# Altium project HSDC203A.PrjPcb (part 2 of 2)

## Sheet HSDC203A_Hub_EZFET.SchDoc: USB Hub and EZFET
size 431 x 279 mm; Date: Not shown in title block; ApprovedBy: Not shown in title block; CheckedBy: Not shown in title block; Author: Not shown in title block; CompanyName: Not shown in title block; Engineer: Not shown in title block; Organization: Not shown in title block; Address1: Not shown in title block; Address2: Not shown in title block; Address3: Not shown in title block; Address4: Not shown in title block; DocumentNumber: 2; Revision: Use project parameter SCH_Rev; SheetNumber: 4; SheetTotal: 7; PageSetup: Record=PageOptions¦CenterHorizontal=True¦CenterVertical=True¦PrintScale=1.00¦XCorrection=1.00¦YCorrection=1.00¦PrintKind=0¦BorderSize=5000000¦LeftOffset=0¦BottomOffset=0¦Orientation=2¦PaperLength=1000¦PaperWidth=1000¦Scale=100¦PaperSource=15¦PrintQuality=600¦MediaType=1¦DitherType=10¦PaperKind=Letter¦PrintScaleMode=1
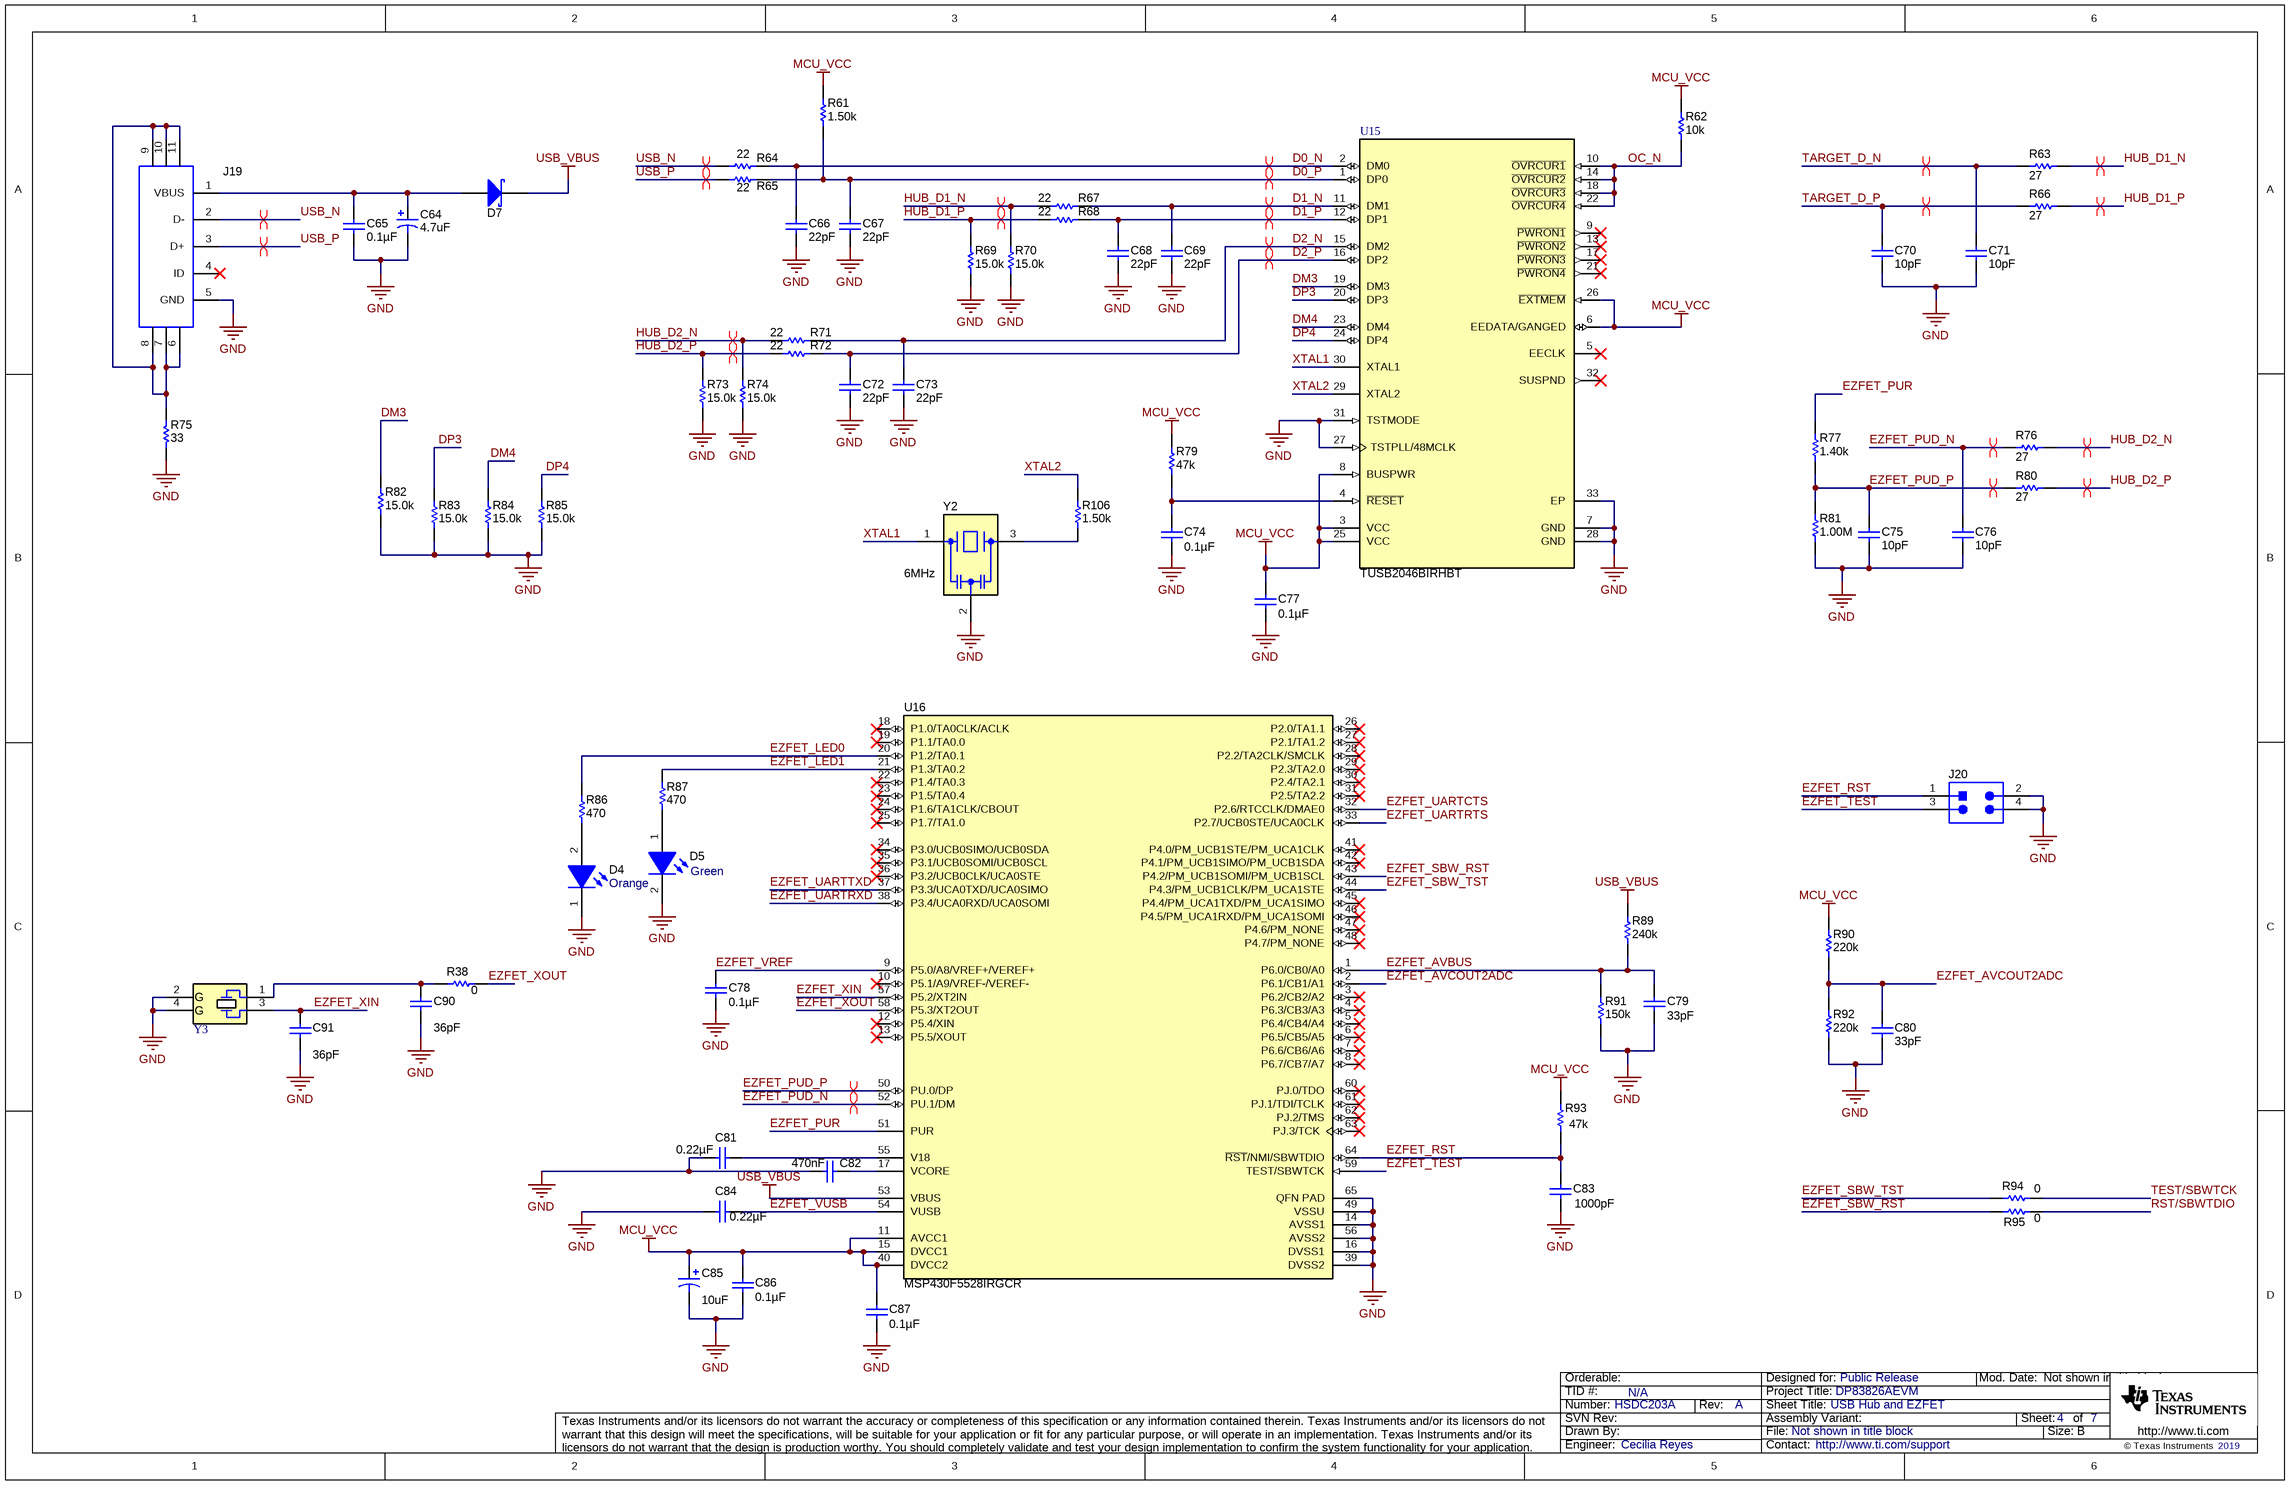
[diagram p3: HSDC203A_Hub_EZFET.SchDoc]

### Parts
C64  ValueDisplayed: 4.7uF  [7343-31]  (hidden comment: 293D475X9035D2TE3)
C65  ValueDisplayed: 0.1µF  [0402]  (hidden comment: C0402C104K8RACTU)
C66  ValueDisplayed: 22pF  [0402]  (hidden comment: C1005NP01H220J050BA)
C67  ValueDisplayed: 22pF  [0402]  (hidden comment: C1005NP01H220J050BA)
C68  ValueDisplayed: 22pF  [0402]  (hidden comment: C1005NP01H220J050BA)
C69  ValueDisplayed: 22pF  [0402]  (hidden comment: C1005NP01H220J050BA)
C70  ValueDisplayed: 10pF  [0603]  (hidden comment: CGA3E2NP01H100D080AA)
C71  ValueDisplayed: 10pF  [0603]  (hidden comment: CGA3E2NP01H100D080AA)
C72  ValueDisplayed: 22pF  [0402]  (hidden comment: C1005NP01H220J050BA)
C73  ValueDisplayed: 22pF  [0402]  (hidden comment: C1005NP01H220J050BA)
C74  ValueDisplayed: 0.1µF  [0402]  (hidden comment: CL05B104KO5NNNC)
C75  ValueDisplayed: 10pF  [0603]  (hidden comment: CGA3E2NP01H100D080AA)
C76  ValueDisplayed: 10pF  [0603]  (hidden comment: CGA3E2NP01H100D080AA)
C77  ValueDisplayed: 0.1µF  [0402]  (hidden comment: CL05B104KO5NNNC)
C78  ValueDisplayed: 0.1µF  [0402]  (hidden comment: CL05B104KO5NNNC)
C79  ValueDisplayed: 33pF  [0402]  (hidden comment: GCM1555C1H330JA16D)
C80  ValueDisplayed: 33pF  [0402]  (hidden comment: GCM1555C1H330JA16D)
C81  ValueDisplayed: 0.22µF  [0603]  (hidden comment: CL10A224KB8NNNC)
C82  Cap_F: 470nF  [0603]  (hidden comment: CGA3E3X7R1H474K080AB)
C83  ValueDisplayed: 1000pF  [0402]  (hidden comment: C1005NP01H102J050BA)
C84  ValueDisplayed: 0.22µF  [0603]  (hidden comment: CL10A224KB8NNNC)
C85  ValueDisplayed: 10uF  [7343-31]  (hidden comment: TPSD106K035R0125)
C86  ValueDisplayed: 0.1µF  [0402]  (hidden comment: CL05B104KO5NNNC)
C87  ValueDisplayed: 0.1µF  [0402]  (hidden comment: CL05B104KO5NNNC)
C90  ValueDisplayed: 36pF  [0402]  (hidden comment: CL05C360JB5NNNC)
C91  ValueDisplayed: 36pF  [0402]  (hidden comment: CL05C360JB5NNNC)
D4  value Orange  [APHHS1005_Orange]  (hidden comment: APHHS1005SECK)
D5  value Green  [QTLP630C_Green]  (hidden comment: QTLP630C4TR)
D7  NRVBA160T3G  [SMA]  (value not drawn)
J19  475890001  [Molex_0475890001]  (value not drawn)
J20  TSW-102-07-G-D  [TSW-102-07-G-D]  (value not drawn)
R38  ValueDisplayed: 0  [0402]  (hidden comment: RC0402JR-070RL)
R61  ValueDisplayed: 1.50k  [0402]  (hidden comment: CRCW04021K50FKED)
R62  ValueDisplayed: 10k  [0402]  (hidden comment: CRCW040210K0JNED)
R63  ValueDisplayed: 27  [0402]  (hidden comment: CRCW040227R0JNED)
R64  ValueDisplayed: 22  [0402]  (hidden comment: CRCW040222R0JNED)
R65  ValueDisplayed: 22  [0402]  (hidden comment: CRCW040222R0JNED)
R66  ValueDisplayed: 27  [0402]  (hidden comment: CRCW040227R0JNED)
R67  ValueDisplayed: 22  [0402]  (hidden comment: CRCW040222R0JNED)
R68  ValueDisplayed: 22  [0402]  (hidden comment: CRCW040222R0JNED)
R69  ValueDisplayed: 15.0k  [0402]  (hidden comment: CRCW040215K0FKED)
R70  ValueDisplayed: 15.0k  [0402]  (hidden comment: CRCW040215K0FKED)
R71  ValueDisplayed: 22  [0402]  (hidden comment: CRCW040222R0JNED)
R72  ValueDisplayed: 22  [0402]  (hidden comment: CRCW040222R0JNED)
R73  ValueDisplayed: 15.0k  [0402]  (hidden comment: CRCW040215K0FKED)
R74  ValueDisplayed: 15.0k  [0402]  (hidden comment: CRCW040215K0FKED)
R75  ValueDisplayed: 33  [0402]  (hidden comment: CRCW040233R0JNED)
R76  ValueDisplayed: 27  [0402]  (hidden comment: CRCW040227R0JNED)
R77  ValueDisplayed: 1.40k  [0402]  (hidden comment: CRCW04021K40FKED)
R79  ValueDisplayed: 47k  [0402]  (hidden comment: CRCW040247K0JNED)
R80  ValueDisplayed: 27  [0402]  (hidden comment: CRCW040227R0JNED)
R81  ValueDisplayed: 1.00M  [0402]  (hidden comment: CRCW04021M00FKED)
R82  ValueDisplayed: 15.0k  [0402]  (hidden comment: CRCW040215K0FKED)
R83  ValueDisplayed: 15.0k  [0402]  (hidden comment: CRCW040215K0FKED)
R84  ValueDisplayed: 15.0k  [0402]  (hidden comment: CRCW040215K0FKED)
R85  ValueDisplayed: 15.0k  [0402]  (hidden comment: CRCW040215K0FKED)
R86  ValueDisplayed: 470  [0402]  (hidden comment: CRCW0402470RJNED)
R87  ValueDisplayed: 470  [0402]  (hidden comment: CRCW0402470RJNED)
R89  ValueDisplayed: 240k  [0402]  (hidden comment: CRCW0402240KJNED)
R90  ValueDisplayed: 220k  [0402]  (hidden comment: CRCW0402220KJNED)
R91  ValueDisplayed: 150k  [0402]  (hidden comment: CRCW0402150KJNED)
R92  ValueDisplayed: 220k  [0402]  (hidden comment: CRCW0402220KJNED)
R93  ValueDisplayed: 47k  [0402]  (hidden comment: CRCW040247K0JNED)
R94  ValueDisplayed: 0  [0402]  (hidden comment: RC0402JR-070RL)
R95  ValueDisplayed: 0  [0402]  (hidden comment: RC0402JR-070RL)
R106  ValueDisplayed: 1.50k  [0402]  (hidden comment: CRCW04021K50FKED)
U15  TUSB2046BIRHBT  [RHB0032E]
U16  MSP430F5528IRGCR  [RGC0064B]
Y2  Frequency_Fixed: 6MHz  [Murata_CSTCR_G]  (hidden comment: CSTCR6M00G53Z-R0)
Y3  ECS-240-20-33-DU-TR  [ECS_ECX-32]  (value not drawn)

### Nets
GND: C64.2(-) C65.1 C66.2 C67.2 C68.2 C69.2 C70.1 C71.1 C72.2 C73.2 C74.2 C75.2 C76.2 C77.2 C78.2 C79.2 C80.2 C81.2 C82.2 C83.2 C84.2 C85.2(-) C86.2 C87.2 C90.2 C91.2 D4.1(K) D5.2(K) J19.5(GND) J20.2 J20.4 R69.1 R70.1 R73.1 R74.1 R75.2 R81.1 R82.1 R83.1 R84.1 R85.1 R91.1 R92.1 U15.7(GND) U15.27(TSTPLL/48MCLK) U15.28(GND) U15.31(TSTMODE) U15.33(EP) U16.14(AVSS1) U16.16(DVSS1) U16.39(DVSS2) U16.49(VSSU) U16.56(AVSS2) U16.65(QFN_PAD) Y2.2(GND) Y3.2(GND) Y3.4(GND)
MCU_VCC: C77.1 C85.1(+) C86.1 C87.1 R61.2 R62.2 R79.2 R90.2 R93.2 U15.3(VCC) U15.6(EEDATA/GANGED) U15.8(BUSPWR) U15.25(VCC) U15.26(~{EXTMEM}) U16.11(AVCC1) U16.15(DVCC1) U16.40(DVCC2)
USB_VBUS: D7.1(K) R89.2 U16.53(VBUS)
D0_N: C66.1 R64.2 U15.2(DM0)
D0_P: C67.1 R61.1 R65.2 U15.1(DP0)
D1_N: C69.1 R67.2 U15.11(DM1)
D1_P: C68.1 R68.2 U15.12(DP1)
D2_N: C73.1 R71.2 U15.15(DM2)
D2_P: C72.1 R72.2 U15.16(DP2)
DM3: R82.2 U15.19(DM3)
DM4: R84.2 U15.23(DM4)
DP3: R83.2 U15.20(DP3)
DP4: R85.2 U15.24(DP4)
EZFET_AVBUS: C79.1 R89.1 R91.2 U16.1(P6.0/CB0/A0)
EZFET_AVCOUT2ADC: C80.1 R90.1 R92.2 U16.2(P6.1/CB1/A1)
EZFET_LED0: R86.2 U16.20(P1.2/TA0.1)
EZFET_LED1: R87.2 U16.21(P1.3/TA0.2)
EZFET_PUD_N: C76.1 R76.1 U16.52(PU.1/DM)
EZFET_PUD_P: C75.1 R77.1 R80.1 R81.2 U16.50(PU.0/DP)
EZFET_PUR: R77.2 U16.51(PUR)
EZFET_RST: C83.1 J20.1 R93.1 U16.64(~{RST}/NMI/SBWTDIO)
EZFET_SBW_RST: R95.1 U16.43(P4.2/PM_UCB1SOMI/PM_UCB1SCL)
EZFET_SBW_TST: R94.1 U16.44(P4.3/PM_UCB1CLK/PM_UCA1STE)
EZFET_TEST: J20.3 U16.59(TEST/SBWTCK)
EZFET_UARTCTS: U16.32(P2.6/RTCCLK/DMAE0)
EZFET_UARTRTS: U16.33(P2.7/UCB0STE/UCA0CLK)
EZFET_UARTRXD: U16.38(P3.4/UCA0RXD/UCA0SOMI)
EZFET_UARTTXD: U16.37(P3.3/UCA0TXD/UCA0SIMO)
EZFET_VREF: C78.1 U16.9(P5.0/A8/VREF+/VEREF+)
EZFET_VUSB: C84.1 U16.54(VUSB)
EZFET_XIN: C91.1 U16.57(P5.2/XT2IN) Y3.3
EZFET_XOUT: R38.2 U16.58(P5.3/XT2OUT)
HUB_D1_N: R63.2 R67.1 R70.2
HUB_D1_P: R66.2 R68.1 R69.2
HUB_D2_N: R71.1 R74.2 R76.2
HUB_D2_P: R72.1 R73.2 R80.2
OC_N: R62.1 U15.10(~{OVRCUR1}) U15.14(~{OVRCUR2}) U15.18(~{OVRCUR3}) U15.22(~{OVRCUR4})
RST/SBWTDIO: R95.2
TARGET_D_N: C71.2 R63.1
TARGET_D_P: C70.2 R66.1
TEST/SBWTCK: R94.2
USB_N: J19.2(D-) R64.1
USB_P: J19.3(D+) R65.1
XTAL1: U15.30(XTAL1) Y2.1(In)
XTAL2: R106.2 U15.29(XTAL2)
NetC64_1: C64.1(+) C65.2 D7.2(A) J19.1(VBUS)
NetC74_1: C74.1 R79.1 U15.4(~{RESET})
NetC81_1: C81.1 U16.55(V18)
NetC82_1: C82.1 U16.17(VCORE)
NetC90_1: C90.1 R38.1 Y3.1
NetD4_2: D4.2(A) R86.1
NetD5_1: D5.1(A) R87.1
NetJ19_6: J19.6 J19.7 J19.8 J19.9 J19.10 J19.11 R75.1
NetR106_1: R106.1 Y2.3(Out)

Not connected (* = marked no-connect by the designer): J19 4(ID)*; U15 5(EECLK)* 9(~{PWRON1})* 13(~{PWRON2})* 17(~{PWRON3})* 21(~{PWRON4})* 32(SUSPND)*; U16 3(P6.2/CB2/A2)* 4(P6.3/CB3/A3)* 5(P6.4/CB4/A4)* 6(P6.5/CB5/A5)* 7(P6.6/CB6/A6)* 8(P6.7/CB7/A7)* 10(P5.1/A9/VREF-/VEREF-)* 12(P5.4/XIN)* 13(P5.5/XOUT)* 18(P1.0/TA0CLK/ACLK)* 19(P1.1/TA0.0)* 22(P1.4/TA0.3)* 23(P1.5/TA0.4)* 24(P1.6/TA1CLK/CBOUT)* 25(P1.7/TA1.0)* 26(P2.0/TA1.1)* 27(P2.1/TA1.2)* 28(P2.2/TA2CLK/SMCLK)* 29(P2.3/TA2.0)* 30(P2.4/TA2.1)* 31(P2.5/TA2.2)* 34(P3.0/UCB0SIMO/UCB0SDA)* 35(P3.1/UCB0SOMI/UCB0SCL)* 36(P3.2/UCB0CLK/UCA0STE)* 41(P4.0/PM_UCB1STE/PM_UCA1CLK)* 42(P4.1/PM_UCB1SIMO/PM_UCB1SDA)* 45(P4.4/PM_UCA1TXD/PM_UCA1SIMO)* 46(P4.5/PM_UCA1RXD/PM_UCA1SOMI)* 47(P4.6/PM_NONE)* 48(P4.7/PM_NONE)* 60(PJ.0/TDO)* 61(PJ.1/TDI/TCLK)* 62(PJ.2/TMS)* 63(PJ.3/TCK)*

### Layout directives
differential pair: D0_N, D0_P, D1_N, D1_P, D2_N, D2_P, EZFET_PUD_N, EZFET_PUD_P, HUB_D1_N, HUB_D1_P, HUB_D2_N, HUB_D2_P, TARGET_D_N, TARGET_D_P, USB_N, USB_P

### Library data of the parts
C64 = CMP-0011708-2: CAP, TA, 4.7 uF, 35 V, +/- 10%, 1.3 ohm, SMD; Manufacturer: Vishay-Sprague; Polarized: Y; CompType: Capacitor; Value: 4.7uF; U/M: EA; Cap_F: 4.7µF; Value1: 1.3 ohm; VDC_V: 35V; ESR_ohm: 1.3; IRMS_A: 3.4dA; TaMin_C: -55°C; TaMax_C: 125°C; Cap_Case: D; AEC Category: Q200; SizeAreaWB_mm2: 58.59; SizeArea_mm2: 31.39; SizeX_mm: 7.3; SizeY_mm: 4.3; SizeZ_mm: 3.1
C65 = CMP-0078241-1: CAP, CERM, 0.1 µF, 10 V,+/- 10%, X7R, 0402; Manufacturer: Kemet; Polarized: N; Value: 0.1uF; U/M: EA; Cap_F: 100nF; VDC_V: 10V; TaMin_C: -55°C; TaMax_C: 125°C; AEC Category: Q200; SizeArea_mm2: 0.5; SizeAreaWB_mm2: 3; SizeX_mm: 1; SizeZ_mm: 0.6
C66-C69 C72 C73 = CMP-0860896-1: CAP, CERM, 22 pF, 50 V,+/- 5%, C0G/NP0, 0402; Manufacturer: TDK; SizeAreaWB_mm2: 3; SizeX_mm: 1; Polarized: N; Value2: 50V; AEC Category: Q200; TaMin_C: -55°C; SizeArea_mm2: 0.5; U/M: EA; SizeZ_mm: 0.6; TaMax_C: 150°C; Value: 22pF
C70 C71 = CMP-0007074-4: CAP, CERM, 10 pF, 50 V, +/- 5%, C0G/NP0, 0603; Manufacturer: TDK; Polarized: N; Value: 10pF; U/M: EA; Value1: Unknown; VDC_V: 50V; TaMin_C: -55°C; TaMax_C: 150°C; SizeArea_mm2: 1.28; SizeAreaWB_mm2: 4.68; SizeX_mm: 1.6; SizeY_mm: 0.8; SizeZ_mm: 1; AEC Category: Q200
C74 C77 C78 C86 C87 = CMP-0085850-1: CAP, CERM, 0.1 µF, 16 V,+/- 10%, X7R, 0402; Manufacturer: Walsin; SizeZ_mm: 0.6; SizeX_mm: 1; AEC Category: Q200; AEC Qualified: N; SizeY_mm: 0.5; VDC_V: 16V; Value: 0.1uF; Cap_F: 100nF; U/M: EA; SizeAreaWB_mm2: 3; TaMin_C: -55°C; TaMax_C: 125°C
C75 C76 = CMP-0007074-4: CAP, CERM, 10 pF, 50 V, +/- 5%, C0G/NP0, 0603; Manufacturer: TDK; TaMin_C: -55°C; Polarized: N; SizeAreaWB_mm2: 4.68; Value1: Unknown; U/M: EA; Value: 10pF; TaMax_C: 150°C; SizeZ_mm: 1; SizeX_mm: 1.6; SizeY_mm: 0.8; Value2: 50V; SizeArea_mm2: 1.28; AEC Category: Q200
C79 C80 = CMP-0860833-1: CAP, CERM, 33 pF, 50 V,+/- 5%, C0G/NP0, AEC-Q200 Grade 1, 0402; Manufacturer: MuRata; U/M: EA; AEC Grade: 1; SizeAreaWB_mm2: 3; TaMin_C: -55°C; VDC_V: 50V; SizeY_mm: 0.5; Value: 33pF; SizeZ_mm: 0.6; AEC Category: Q200; Polarized: N; TaMax_C: 125°C; AEC Qualified: Y
C81 C84 = CMP-0860899-1: CAP, CERM, 0.22 µF, 50 V,+/- 10%, X5R, 0603; Manufacturer: Samsung Electro-Mechanics; Cap_F: 220nF; U/M: EA; TaMax_C: 85°C; SizeAreaWB_mm2: 4.68; VDC_V: 50V; Value: 0.22uF; Polarized: N; AEC Category: Q200; SizeArea_mm2: 1.28; SizeY_mm: 0.8; SizeX_mm: 1.6; TaMin_C: -55°C; SizeZ_mm: 1
C82 = CMP-0007096-4: CAP, CERM, 0.47 uF, 50 V, +/- 10%, X7R, AEC-Q200 Grade 1, 0603; Manufacturer: TDK; TaMin_C: -55°C; ESR_ohm: 0.01064; Polarized: N; SizeAreaWB_mm2: 4.68; Value1: 0.01064 ohm; U/M: EA; Value: 0.47uF; TaMax_C: 125°C; SizeZ_mm: 1; SizeX_mm: 1.6; SizeY_mm: 0.8; Value2: 50V; SizeArea_mm2: 1.28; AEC Qualified: Y; IRMS_A: 1.59966A; AEC Category: Q200
C83 = CMP-0006254-2: CAP, CERM, 1000 pF, 50 V, +/- 5%, C0G/NP0, 0402; Manufacturer: TDK; TaMin_C: -55°C; Polarized: N; SizeAreaWB_mm2: 3; Value1: Unknown; U/M: EA; Value: 1000pF; TaMax_C: 150°C; SizeZ_mm: 0.6; SizeX_mm: 1; SizeY_mm: 0.5; Value2: 50V; Cap_F: 1nF; AEC Category: Q200
C85 = CMP-0011855-2: CAP, TA, 10 uF, 35 V, +/- 10%, 0.125 ohm, SMD; Manufacturer: AVX; TaMin_C: -55°C; ESR_ohm: 0.125; Polarized: Y; SizeAreaWB_mm2: 58.59; U/M: EA; Value: 10uF; TaMax_C: 125°C; SizeZ_mm: 3.1; SizeX_mm: 7.3; SizeY_mm: 4.3; Cap_Case: D; Value2: 35V; SizeArea_mm2: 31.39; CompType: Capacitor; Cap_F: 10µF; IRMS_A: 986mA; AEC Category: Q200
C90 C91 = CMP-0083839-1: CAP, CERM, 36 pF, 50 V,+/- 5%, C0G/NP0, 0402; Manufacturer: Samsung Electro-Mechanics; SizeAreaWB_mm2: 3; SizeArea_mm2: 0.5; AEC Qualified: N; AEC Category: Q200; Value: 36pF; TaMax_C: 125°C; SizeZ_mm: 0.6; TaMin_C: -55°C; VDC_V: 50V; U/M: EA; SizeX_mm: 1
D4 = CMP-0077734-1: LED, Orange, SMD; Manufacturer: Kingbright; Tjmax_C: 85°C; SizeAreaWB_mm2: 3; Vr_V: 5V; Power_TotalModule: 75mW; Angle: 120; SizeArea_mm2: 0.5; Ir_A: 10µA; SizeZ_mm: 0.6; Io_A: 20mA; Vf_V: 2.1V; U/M: EA; Value1: .075W; SizeX_mm: 1
D5 = CMP-0002917-2: LED, Green, SMD; Manufacturer: Everlight; Value2: 2.1V; Io_A: 20mA; Tjmax_C: 85°C; Value1: W; Vr_V: 5V; Angle: 140
D7 = CMP-0028762-2: Diode, Schottky, 60 V, 1 A, AEC-Q101, SMA; Manufacturer: ON Semiconductor; Vf_V: 510mV; Value: 60V; Value1: 1A; Value2: 0.51V; TJmax_C: 150°C; AEC Category: Q101; AEC Qualified: Y; Green_Lifecycle: Active; Green_REACh: Passed; SizeArea_mm2: 16.3228; SizeAreaWB_mm2: 37.3428; SizeX_mm: 5.59; SizeY_mm: 2.92; SizeZ_mm: 2.87
J19 = CMP-0055301-1: Connector, Receptacle, Micro-USB Type AB, R/A, Bottom Mount SMT; Manufacturer: Molex; CompType: USB; Gender: Female; CNHeader: FALSE; CT: TRUE; Green_Lifecycle: Active; Green_REACh: Passed
J20 = CMP-0075404-1: Header, 100mil, 2x2, Gold, TH; Manufacturer: Samtec; Pitch_mm: 2.54; Cert_VDE: N; Gender: Male; Cert_CSA: Y; Voltage_V: 550V; Green_REACh: Passed; Current_A: 6.3A; CT: False; Green_Lifecycle: Active; Row_Count: 2; CNHeader: True
R38 R94 R95 = CMP-0027004-2: RES, 0, 5%, 0.063 W, 0402; Manufacturer: Yageo America; Power_W: 63mW; TempCo: 200 ppm/C; Value_Code: 0000; U/M: EA; Value: 0; EIA_Code: E24; SizeX_mm: 1; SizeY_mm: 0.5; SizeZ_mm: 0.6; Value2: 0.063W; VDC_V: 50V; AEC Category: Q200
R61 R106 = CMP-0026088-3: RES, 1.50 k, 1%, 0.063 W, AEC-Q200 Grade 0, 0402; Manufacturer: Vishay-Dale; Power_W: 63mW; TempCo: 100 ppm/C; Value_Code: 1k50; Value: 1.50k; EIA_Code: E96; Res_ohm: 1.5k; SizeX_mm: 1; SizeY_mm: 0.5; SizeZ_mm: 0.6; Value2: 0.063W; AEC Qualified: Y; VDC_V: 50V; AEC Category: Q200; AEC Grade: 0
R62 = CMP-0026825-5: RES, 10 k, 5%, 0.063 W, AEC-Q200 Grade 0, 0402; Manufacturer: Vishay-Dale; Power_W: 63mW; TempCo: 200 ppm/C; Value_Code: 10k0; Value: 10k; EIA_Code: E24; SizeX_mm: 1; SizeY_mm: 0.5; SizeZ_mm: 0.6; Value2: 0.063W; AEC Qualified: Y; VDC_V: 50V; AEC Category: Q200; AEC Grade: 0
R63 R66 = CMP-0026888-3: RES, 27, 5%, 0.063 W, AEC-Q200 Grade 0, 0402; Manufacturer: Vishay-Dale; Value: 27; Value_Code: 27R0; Power_W: 63mW; Value2: 0.063W; VDC_V: 50V; TempCo: 200 ppm/C; EIA_Code: E24; AEC Category: Q200; AEC Qualified: Y; AEC Grade: 0; SizeArea_mm2: 0.5; SizeX_mm: 1; SizeZ_mm: 0.6
R64 R65 R67 R68 R71 R72 = CMP-0026880-3: RES, 22, 5%, 0.063 W, AEC-Q200 Grade 0, 0402; Manufacturer: Vishay-Dale; Power_W: 63mW; TempCo: 200 ppm/C; Value_Code: 22R0; Value: 22; EIA_Code: E24; SizeX_mm: 1; SizeY_mm: 0.5; SizeZ_mm: 0.6; Value2: 0.063W; AEC Qualified: Y; VDC_V: 50V; AEC Category: Q200; AEC Grade: 0
R69 R70 R73 R74 R82-R85 = CMP-0026027-3: RES, 15.0 k, 1%, 0.063 W, AEC-Q200 Grade 0, 0402; Manufacturer: Vishay-Dale; Power_W: 63mW; TempCo: 100 ppm/C; Value_Code: 15k0; Value: 15.0k; EIA_Code: E96; Res_ohm: 15k; SizeX_mm: 1; SizeY_mm: 0.5; SizeZ_mm: 0.6; Value2: 0.063W; AEC Qualified: Y; VDC_V: 50V; AEC Category: Q200; AEC Grade: 0
R75 = CMP-0026908-3: RES, 33, 5%, 0.063 W, AEC-Q200 Grade 0, 0402; Manufacturer: Vishay-Dale; Value: 33; Value_Code: 33R0; Power_W: 63mW; Value2: 0.063W; VDC_V: 50V; TempCo: 200 ppm/C; EIA_Code: E24; AEC Category: Q200; AEC Qualified: Y; AEC Grade: 0; SizeArea_mm2: 0.5; SizeX_mm: 1; SizeZ_mm: 0.6
R76 R80 = CMP-0026888-3: RES, 27, 5%, 0.063 W, AEC-Q200 Grade 0, 0402; Manufacturer: Vishay-Dale; Power_W: 63mW; TempCo: 200 ppm/C; Value_Code: 27R0; Value: 27; EIA_Code: E24; SizeX_mm: 1; SizeY_mm: 0.5; SizeZ_mm: 0.6; Value2: 0.063W; AEC Qualified: Y; VDC_V: 50V; AEC Category: Q200; AEC Grade: 0
R77 = CMP-0026085-3: RES, 1.40 k, 1%, 0.063 W, AEC-Q200 Grade 0, 0402; Manufacturer: Vishay-Dale; Power_W: 63mW; TempCo: 100 ppm/C; Value_Code: 1k40; Value: 1.40k; EIA_Code: E96; Res_ohm: 1.4k; SizeX_mm: 1; SizeY_mm: 0.5; SizeZ_mm: 0.6; Value2: 0.063W; AEC Qualified: Y; VDC_V: 50V; AEC Category: Q200; AEC Grade: 0
R79 R93 = CMP-0026935-3: RES, 47 k, 5%, 0.063 W, AEC-Q200 Grade 0, 0402; Manufacturer: Vishay-Dale; Power_W: 63mW; TempCo: 200 ppm/C; Value_Code: 47k0; Value: 47k; EIA_Code: E24; SizeX_mm: 1; SizeY_mm: 0.5; SizeZ_mm: 0.6; Value2: 0.063W; AEC Qualified: Y; VDC_V: 50V; AEC Category: Q200; AEC Grade: 0
R81 = CMP-0026100-2: RES, 1.00 M, 1%, 0.063 W, AEC-Q200 Grade 0, 0402; Manufacturer: Vishay-Dale; Power_W: 63mW; TempCo: 100 ppm/C; Value_Code: 1M00; Value: 1.00Meg; EIA_Code: E96; Res_ohm: 1M; SizeX_mm: 1; SizeY_mm: 0.5; SizeZ_mm: 0.6; Value2: 0.063W; AEC Qualified: Y; VDC_V: 50V; AEC Category: Q200; AEC Grade: 0
R86 R87 = CMP-0026934-3: RES, 470, 5%, 0.063 W, AEC-Q200 Grade 0, 0402; Manufacturer: Vishay-Dale; Power_W: 63mW; TempCo: 200 ppm/C; Value_Code: 470R; Value: 470; EIA_Code: E24; SizeX_mm: 1; SizeY_mm: 0.5; SizeZ_mm: 0.6; Value2: 0.063W; AEC Qualified: Y; VDC_V: 50V; AEC Category: Q200; AEC Grade: 0
R89 = CMP-0026881-2: RES, 240 k, 5%, 0.063 W, AEC-Q200 Grade 0, 0402; Manufacturer: Vishay-Dale; Power_W: 63mW; TempCo: 200 ppm/C; Value: 240k; EIA_Code: E24; SizeX_mm: 1; SizeY_mm: 0.5; SizeZ_mm: 0.6; Value2: 0.063W; AEC Qualified: Y; VDC_V: 50V; AEC Category: Q200; AEC Grade: 0
R90 R92 = CMP-0026877-2: RES, 220 k, 5%, 0.063 W, AEC-Q200 Grade 0, 0402; Manufacturer: Vishay-Dale; Power_W: 63mW; TempCo: 200 ppm/C; Value: 220k; EIA_Code: E24; SizeX_mm: 1; SizeY_mm: 0.5; SizeZ_mm: 0.6; Value2: 0.063W; AEC Qualified: Y; VDC_V: 50V; AEC Category: Q200; AEC Grade: 0
R91 = CMP-0026840-2: RES, 150 k, 5%, 0.063 W, AEC-Q200 Grade 0, 0402; Manufacturer: Vishay-Dale; Power_W: 63mW; TempCo: 200 ppm/C; Value: 150k; EIA_Code: E24; SizeX_mm: 1; SizeY_mm: 0.5; SizeZ_mm: 0.6; Value2: 0.063W; AEC Qualified: Y; VDC_V: 50V; AEC Category: Q200; AEC Grade: 0
U15 = CMP-0033743-2: 4-Port Full-Speed USB Hub, 3.3V, -40 to 85 degC, 32-Pin QFN (RHB), Green (RoHS & no Sb/Br); Manufacturer: Texas Instruments; SubFamily: USB Hub Controller; Supply Voltage(s)(V): 3.3; USB Speed: Full; USB Full Speed: True
U16 = CMP-0039268-4: 16-Bit Ultra-Low-Power Microcontroller, 128KB Flash, 8KB RAM, USB, 12Bit ADC, 2 USCIs, 32Bit HW MPY, RGC0064B (VQFN-64); Manufacturer: Texas Instruments; ADC: 12-bit SAR; Flash(KB): 128; CompType: IC; USB: 1; Rating: Catalog; Frequency(MHz): 25; GPIO: 47; SVS: Yes; SizeAreaWB_mm2: 121.0; USCI_B (I2C & SPI): 2; DMA: 3; AEC Qualified: N; Timers - 16-bit: 4; SizeX_mm: 9.0; AEC Category: Q200; ADC Channels: 16; SizeArea_mm2: 81.0; Multiplier: 32x32; SRAM(B): 8192; SizeZ_mm: 1.0
Y2 = CMP-0006147-4: Resonator, 6 MHz, 15pF SMD; Manufacturer: MuRata; TaMin_C: -40°C; Frequency Stability: +/-0.2 %; TaMax_C: 125°C; AEC Category: Q200; AEC Qualified: N
Y3 = CMP-0004637-3: Crystal, 24 MHz, 20pF, SMD; Manufacturer: ECS Inc.; TaMin_C: -55°C; Frequency Stability: +/-100ppm; Frequency_Fixed: 24MHz; TaMax_C: 125°C

## Sheet HSDC203A_Coms.SchDoc: MSP430 and SMI
size 431 x 279 mm; Date: Not shown in title block; ApprovedBy: Not shown in title block; CheckedBy: Not shown in title block; Author: Not shown in title block; CompanyName: Not shown in title block; DrawnBy: Aniruddha Khadye; Engineer: Not shown in title block; Organization: Not shown in title block; Address1: Not shown in title block; Address2: Not shown in title block; Address3: Not shown in title block; Address4: Not shown in title block; DocumentNumber: 4; Revision: Use project parameter SCH_Rev; SheetNumber: 5; SheetTotal: 7; PageSetup: Record=PageOptions¦CenterHorizontal=True¦CenterVertical=True¦PrintScale=1.00¦XCorrection=1.00¦YCorrection=1.00¦PrintKind=0¦BorderSize=5000000¦LeftOffset=0¦BottomOffset=0¦Orientation=2¦PaperLength=1000¦PaperWidth=1000¦Scale=100¦PaperSource=15¦PrintQuality=600¦MediaType=1¦DitherType=10¦PaperKind=Letter¦PrintScaleMode=1
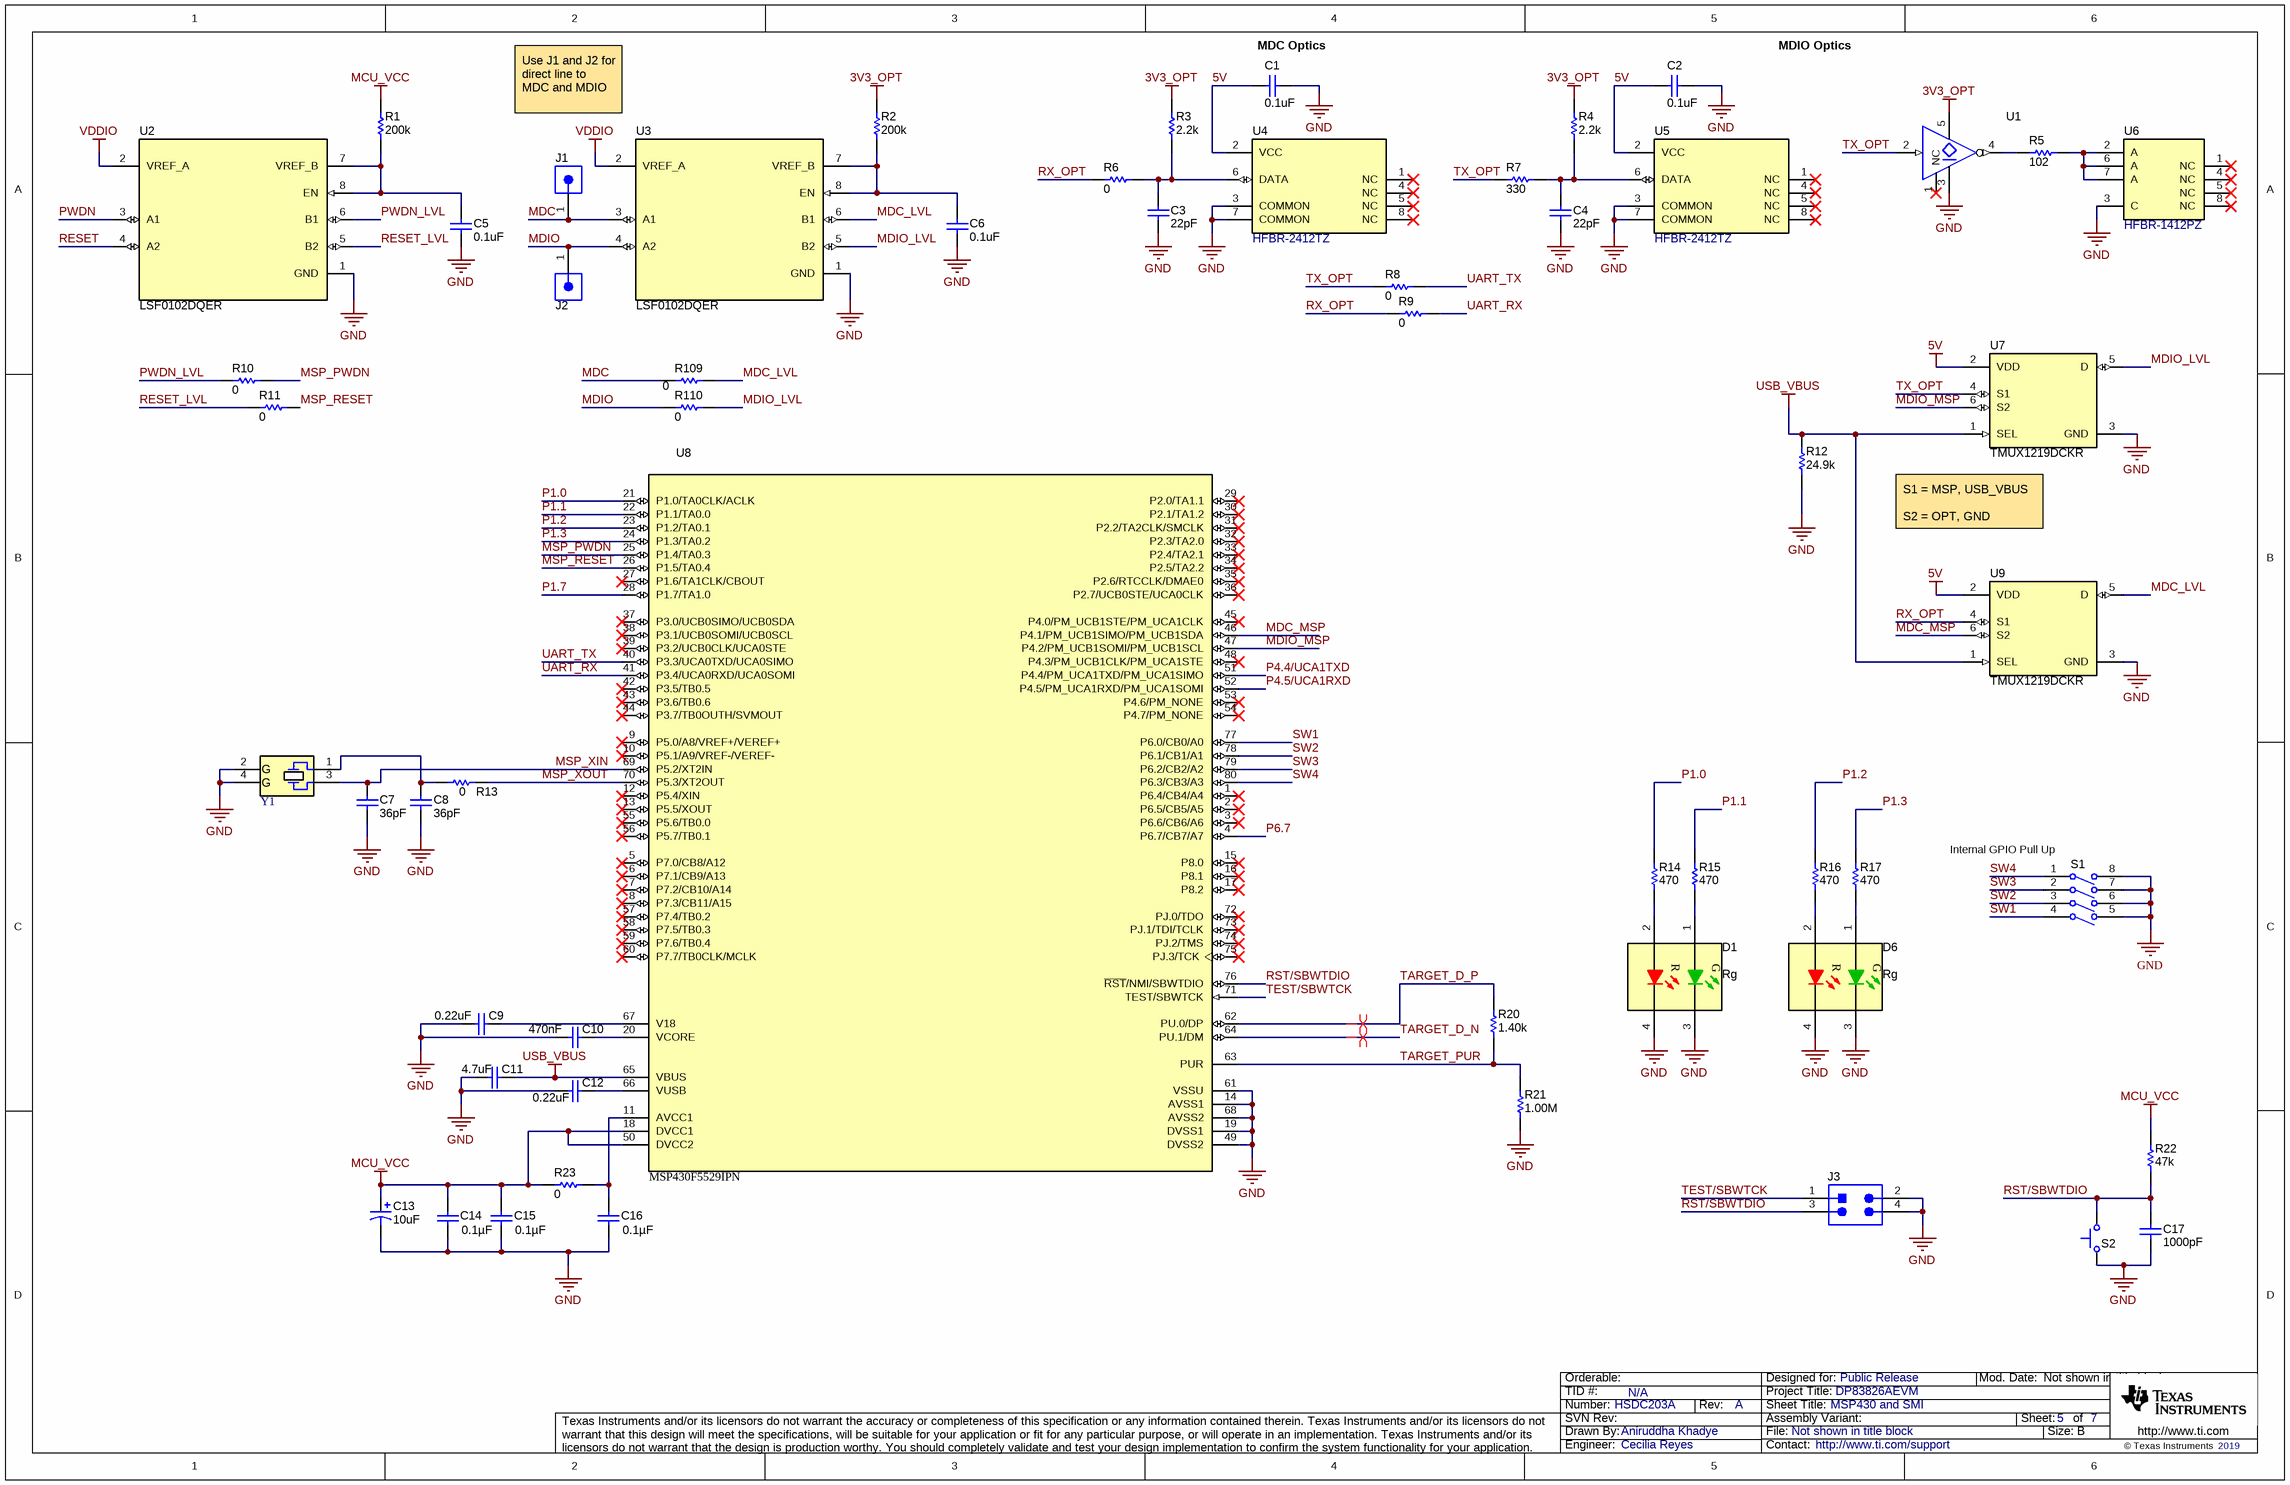
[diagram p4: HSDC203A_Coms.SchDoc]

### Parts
C1  ValueDisplayed: 0.1uF  [0402]  (hidden comment: GCM155R71H104KE02D)
C2  ValueDisplayed: 0.1uF  [0402]  (hidden comment: GCM155R71H104KE02D)
C3  ValueDisplayed: 22pF  [0603]  (hidden comment: CGA3E2C0G1H220J080AA)
C4  ValueDisplayed: 22pF  [0603]  (hidden comment: CGA3E2C0G1H220J080AA)
C5  ValueDisplayed: 0.1uF  [0402]  (hidden comment: GCM155R71H104KE02D)
C6  ValueDisplayed: 0.1uF  [0402]  (hidden comment: GCM155R71H104KE02D)
C7  ValueDisplayed: 36pF  [0402]  (hidden comment: CL05C360JB5NNNC)
C8  ValueDisplayed: 36pF  [0402]  (hidden comment: CL05C360JB5NNNC)
C9  ValueDisplayed: 0.22uF  [0603]  (hidden comment: C0603C224Z4VACTU)
C10  Cap_F: 470nF  [0603]  (hidden comment: GCM188R71C474KA55D)
C11  ValueDisplayed: 4.7uF  [0603]  (hidden comment: C1608X5R1V475K080AC)
C12  ValueDisplayed: 0.22uF  [0603]  (hidden comment: C0603C224Z4VACTU)
C13  ValueDisplayed: 10uF  [7343-31]  (hidden comment: TPSD106K035R0125)
C14  ValueDisplayed: 0.1µF  [0402]  (hidden comment: C0402C104K8RACTU)
C15  ValueDisplayed: 0.1µF  [0402]  (hidden comment: C0402C104K8RACTU)
C16  ValueDisplayed: 0.1µF  [0402]  (hidden comment: C0402C104K8RACTU)
C17  ValueDisplayed: 1000pF  [0402]  (hidden comment: C1005NP01H102J050BA)
D1  value Rg  [HSMF-C165_RG]  (hidden comment: HSMF-C165)
D6  value Rg  [HSMF-C165_RG]  (hidden comment: HSMF-C165)
J1  (no value)  [Sullins_PEC01SAAN]
J2  PEC01SAAN  [Sullins_PEC01SAAN]  (value not drawn)
J3  TSW-102-07-G-D  [TSW-102-07-G-D]  (value not drawn)
R1  ValueDisplayed: 200k  [0603]  (hidden comment: CRCW0603200KJNEA)
R2  ValueDisplayed: 200k  [0603]  (hidden comment: CRCW0603200KJNEA)
R3  ValueDisplayed: 2.2k  [0603]  (hidden comment: ERJ-3GEYJ222V)
R4  ValueDisplayed: 2.2k  [0603]  (hidden comment: ERJ-3GEYJ222V)
R5  ValueDisplayed: 102  [0603]  (hidden comment: CRCW0603102RFKEA)
R6  ValueDisplayed: 0  [0603]  (hidden comment: ERJ-3GEY0R00V)
R7  ValueDisplayed: 330  [0603]  (hidden comment: CRCW0603330RJNEA)
R8  ValueDisplayed: 0  [0402]  (hidden comment: ERJ-2GE0R00X)
R9  ValueDisplayed: 0  [0402]  (hidden comment: ERJ-2GE0R00X)
R10  ValueDisplayed: 0  [0402]  (hidden comment: ERJ-2GE0R00X)
R11  ValueDisplayed: 0  [0402]  (hidden comment: ERJ-2GE0R00X)
R12  ValueDisplayed: 24.9k  [0603]  (hidden comment: CRCW060324K9FKEA)
R13  ValueDisplayed: 0  [0402]  (hidden comment: CRCW04020000Z0ED)
R14  ValueDisplayed: 470  [0201]  (hidden comment: RC0201JR-07470RL)
R15  ValueDisplayed: 470  [0201]  (hidden comment: RC0201JR-07470RL)
R16  ValueDisplayed: 470  [0201]  (hidden comment: RC0201JR-07470RL)
R17  ValueDisplayed: 470  [0201]  (hidden comment: RC0201JR-07470RL)
R20  ValueDisplayed: 1.40k  [0402]  (hidden comment: CRCW04021K40FKED)
R21  ValueDisplayed: 1.00M  [0402]  (hidden comment: CRCW04021M00FKED)
R22  ValueDisplayed: 47k  [0402]  (hidden comment: CRCW040247K0JNED)
R23  ValueDisplayed: 0  [0402]  (hidden comment: CRCW04020000Z0ED)
R109  ValueDisplayed: 0  [0402]  (hidden comment: ERJ-2GE0R00X)
R110  ValueDisplayed: 0  [0402]  (hidden comment: ERJ-2GE0R00X)
S1  218-4LPST  [SW_218-4LPST]  (value not drawn)
S2  KSR221GLFS  [KSR]  (value not drawn)
U1  SN74LVC1G04QDBVRQ1  [DBV0005A_N]  (value not drawn)
U2  LSF0102DQER  [DQE0008A]
U3  LSF0102DQER  [DQE0008A]
U4  HFBR-2412TZ  [HFBR-x41xTZ]
U5  HFBR-2412TZ  [HFBR-x41xTZ]
U6  HFBR-1412PZ  [HFBR-x41xZ]
U7  TMUX1219DCKR  [DCK0006A_N]
U8  MSP430F5529IPN  [PN0080A_N]
U9  TMUX1219DCKR  [DCK0006A_N]
Y1  ECS-240-20-33-DU-TR  [ECS_ECX-32]  (value not drawn)

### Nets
3V3_OPT: R2.2 R3.2 R4.2 U1.5(VCC)
5V: C1.1 C2.1 U4.2(VCC) U5.2(VCC) U7.2(VDD) U9.2(VDD)
GND: C1.2 C2.2 C3.2 C4.2 C5.2 C6.2 C7.2 C8.2 C9.2 C10.2 C11.1 C12.2 C13.2(-) C14.2 C15.2 C16.2 C17.1 D1.3(K) D1.4(K) D6.3(K) D6.4(K) J3.2 J3.4 R12.1 R21.2 S1.5(B4) S1.6(B3) S1.7(B2) S1.8(B1) S2.1 U1.3(GND) U2.1(GND) U3.1(GND) U4.3(COMMON) U4.7(COMMON) U5.3(COMMON) U5.7(COMMON) U6.3(C) U7.3(GND) U8.14(AVSS1) U8.19(DVSS1) U8.49(DVSS2) U8.61(VSSU) U8.68(AVSS2) U9.3(GND) Y1.2(GND) Y1.4(GND)
MCU_VCC: C13.1(+) C14.1 C15.1 R1.2 R22.1 R23.1 U8.18(DVCC1) U8.50(DVCC2)
USB_VBUS: C11.2 R12.2 U7.1(SEL) U8.65(VBUS) U9.1(SEL)
VDDIO: U2.2(VREF_A) U3.2(VREF_A)
MDC: J1.1 R109.1 U3.3(A1)
MDC_LVL: R109.2 U3.6(B1) U9.5(D)
MDC_MSP: U8.46(P4.1/PM_UCB1SIMO/PM_UCB1SDA) U9.6(S2)
MDIO: J2.1 R110.1 U3.4(A2)
MDIO_LVL: R110.2 U3.5(B2) U7.5(D)
MDIO_MSP: U7.6(S2) U8.47(P4.2/PM_UCB1SOMI/PM_UCB1SCL)
MSP_PWDN: R10.2 U8.25(P1.4/TA0.3)
MSP_RESET: R11.2 U8.26(P1.5/TA0.4)
MSP_XIN: C7.1 U8.69(P5.2/XT2IN) Y1.3
MSP_XOUT: R13.2 U8.70(P5.3/XT2OUT)
P1.0: R14.2 U8.21(P1.0/TA0CLK/ACLK)
P1.1: R15.2 U8.22(P1.1/TA0.0)
P1.2: R16.2 U8.23(P1.2/TA0.1)
P1.3: R17.2 U8.24(P1.3/TA0.2)
P1.7: U8.28(P1.7/TA1.0)
P4.4/UCA1TXD: U8.51(P4.4/PM_UCA1TXD/PM_UCA1SIMO)
P4.5/UCA1RXD: U8.52(P4.5/PM_UCA1RXD/PM_UCA1SOMI)
P6.7: U8.4(P6.7/CB7/A7)
PWDN: U2.3(A1)
PWDN_LVL: R10.1 U2.6(B1)
RESET: U2.4(A2)
RESET_LVL: R11.1 U2.5(B2)
RST/SBWTDIO: C17.2 J3.3 R22.2 S2.2 U8.76(~{RST}/NMI/SBWTDIO)
RX_OPT: R6.1 R9.1 U9.4(S1)
SW1: S1.4(A4) U8.77(P6.0/CB0/A0)
SW2: S1.3(A3) U8.78(P6.1/CB1/A1)
SW3: S1.2(A2) U8.79(P6.2/CB2/A2)
SW4: S1.1(A1) U8.80(P6.3/CB3/A3)
TARGET_D_N: U8.64(PU.1/DM)
TARGET_D_P: R20.2 U8.62(PU.0/DP)
TARGET_PUR: R20.1 R21.1 U8.63(PUR)
TEST/SBWTCK: J3.1 U8.71(TEST/SBWTCK)
TX_OPT: R7.1 R8.1 U1.2(A) U7.4(S1)
UART_RX: R9.2 U8.41(P3.4/UCA0RXD/UCA0SOMI)
UART_TX: R8.2 U8.40(P3.3/UCA0TXD/UCA0SIMO)
NetC3_1: C3.1 R3.1 R6.2 U4.6(DATA)
NetC4_1: C4.1 R4.1 R7.2 U5.6(DATA)
NetC5_1: C5.1 R1.1 U2.7(VREF_B) U2.8(EN)
NetC6_1: C6.1 R2.1 U3.7(VREF_B) U3.8(EN)
NetC8_1: C8.1 R13.1 Y1.1
NetC9_1: C9.1 U8.67(V18)
NetC10_1: C10.1 U8.20(VCORE)
NetC12_1: C12.1 U8.66(VUSB)
NetC16_1: C16.1 R23.2 U8.11(AVCC1)
NetD1_1: D1.1(A) R15.1
NetD1_2: D1.2(A) R14.1
NetD6_1: D6.1(A) R17.1
NetD6_2: D6.2(A) R16.1
NetR5_1: R5.1 U6.2(A) U6.6(A) U6.7(A)
NetR5_2: R5.2 U1.4(Y)

Not connected (* = marked no-connect by the designer): U1 1(NC)*; U4 1(NC)* 4(NC)* 5(NC)* 8(NC)*; U5 1(NC)* 4(NC)* 5(NC)* 8(NC)*; U6 1(NC)* 4(NC)* 5(NC)* 8(NC)*; U8 1(P6.4/CB4/A4)* 2(P6.5/CB5/A5)* 3(P6.6/CB6/A6)* 5(P7.0/CB8/A12)* 6(P7.1/CB9/A13)* 7(P7.2/CB10/A14)* 8(P7.3/CB11/A15)* 9(P5.0/A8/VREF+/VEREF+)* 10(P5.1/A9/VREF-/VEREF-)* 12(P5.4/XIN)* 13(P5.5/XOUT)* 15(P8.0)* 16(P8.1)* 17(P8.2)* 27(P1.6/TA1CLK/CBOUT)* 29(P2.0/TA1.1)* 30(P2.1/TA1.2)* 31(P2.2/TA2CLK/SMCLK)* 32(P2.3/TA2.0)* 33(P2.4/TA2.1)* 34(P2.5/TA2.2)* 35(P2.6/RTCCLK/DMAE0)* 36(P2.7/UCB0STE/UCA0CLK)* 37(P3.0/UCB0SIMO/UCB0SDA)* 38(P3.1/UCB0SOMI/UCB0SCL)* 39(P3.2/UCB0CLK/UCA0STE)* 42(P3.5/TB0.5)* 43(P3.6/TB0.6)* 44(P3.7/TB0OUTH/SVMOUT)* 45(P4.0/PM_UCB1STE/PM_UCA1CLK)* 48(P4.3/PM_UCB1CLK/PM_UCA1STE)* 53(P4.6/PM_NONE)* 54(P4.7/PM_NONE)* 55(P5.6/TB0.0)* 56(P5.7/TB0.1)* 57(P7.4/TB0.2)* 58(P7.5/TB0.3)* 59(P7.6/TB0.4)* 60(P7.7/TB0CLK/MCLK)* 72(PJ.0/TDO)* 73(PJ.1/TDI/TCLK)* 74(PJ.2/TMS)* 75(PJ.3/TCK)*

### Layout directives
differential pair: TARGET_D_N, TARGET_D_P

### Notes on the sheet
- (near C1) MDC Optics
- MDIO Optics
- Use J1 and J2 for direct line to MDC and MDIO
- (near U7) S1 = MSP, USB_VBUS
  S2 = OPT, GND
- (near S1) Internal GPIO Pull Up

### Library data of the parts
C1 C2 C5 C6 = CMP-0006356-2: CAP, CERM, 0.1 uF, 50 V, +/- 10%, X7R, AEC-Q200 Grade 1, 0402; Manufacturer: MuRata; TaMin_C: -55°C; Polarized: N; SizeAreaWB_mm2: 3; Value1: Unknown; U/M: EA; Value: 0.1uF; TaMax_C: 125°C; SizeZ_mm: 0.6; SizeX_mm: 1; SizeY_mm: 0.5; Value2: 50V; AEC Qualified: Y; Cap_F: 100nF; AEC Category: Q200
C3 C4 = CMP-0007071-4: CAP, CERM, 22 pF, 50 V, +/- 5%, C0G/NP0, AEC-Q200 Grade 1, 0603; Manufacturer: TDK; TaMin_C: -55°C; Polarized: N; SizeAreaWB_mm2: 4.68; Value1: Unknown; U/M: EA; Value: 22pF; TaMax_C: 125°C; SizeZ_mm: 1; SizeX_mm: 1.6; SizeY_mm: 0.8; Value2: 50V; SizeArea_mm2: 1.28; CompType: Capacitor; AEC Qualified: Y; AEC Category: Q200
C7 C8 = CMP-0083839-1: as C90 on sheet HSDC203A_Hub_EZFET
C9 C12 = CMP-0006905-4: CAP, CERM, 0.22 uF, 16 V, +80/-20%, Y5V, 0603; Manufacturer: Kemet; TaMin_C: -30°C; Polarized: N; SizeAreaWB_mm2: 4.68; Value1: Unknown; U/M: EA; Value: 0.22uF; TaMax_C: 85°C; Tolerance_%: 80%; SizeZ_mm: 1; SizeX_mm: 1.6; SizeY_mm: 0.8; Value2: 16V; SizeArea_mm2: 1.28; Cap_F: 220nF; AEC Category: Q200
C10 = CMP-0007138-4: CAP, CERM, 0.47 uF, 16 V, +/- 10%, X7R, AEC-Q200 Grade 1, 0603; Manufacturer: MuRata; TaMin_C: -55°C; Polarized: N; SizeAreaWB_mm2: 4.68; Value1: Unknown; U/M: EA; Value: 0.47uF; TaMax_C: 125°C; SizeZ_mm: 1; SizeX_mm: 1.6; SizeY_mm: 0.8; Value2: 16V; SizeArea_mm2: 1.28; AEC Qualified: Y; AEC Category: Q200
C11 = CMP-0007022-5: CAP, CERM, 4.7 uF, 35 V, +/- 10%, X5R, 0603; Manufacturer: TDK; Polarized: N; CompType: Capacitor; Value: 4.7uF; U/M: EA; Cap_F: 4.7µF; ESR_ohm: 3.728m; Value1: 0.003728 ohm; VDC_V: 35V; IRMS_A: 2.69359A; TaMin_C: -55°C; TaMax_C: 85°C; SizeArea_mm2: 1.28; SizeAreaWB_mm2: 4.68; SizeX_mm: 1.6; SizeY_mm: 0.8; SizeZ_mm: 1; AEC Category: Q200
C13 = CMP-0011855-2: CAP, TA, 10 uF, 35 V, +/- 10%, 0.125 ohm, SMD; Manufacturer: AVX; Polarized: Y; CompType: Capacitor; Value: 10uF; U/M: EA; Cap_F: 10µF; VDC_V: 35V; ESR_ohm: 1.25d; IRMS_A: 9.86dA; TaMin_C: -55°C; TaMax_C: 125°C; Cap_Case: D; AEC Category: Q200; SizeArea_mm2: 31.39; SizeAreaWB_mm2: 58.59; SizeX_mm: 7.3; SizeY_mm: 4.3; SizeZ_mm: 3.1
C14-C16 = CMP-0078241-1: CAP, CERM, 0.1 µF, 10 V,+/- 10%, X7R, 0402; Manufacturer: Kemet; TaMin_C: -55°C; Polarized: N; SizeAreaWB_mm2: 3; U/M: EA; Value: 0.1uF; TaMax_C: 125°C; SizeZ_mm: 0.6; SizeX_mm: 1; SizeY_mm: 0.5; Value2: 10V; Cap_F: 100nF; AEC Category: Q200
C17 = CMP-0006254-2: CAP, CERM, 1000 pF, 50 V, +/- 5%, C0G/NP0, 0402; Manufacturer: TDK; Polarized: N; Value: 1000pF; U/M: EA; Cap_F: 1nF; Value1: Unknown; VDC_V: 50V; TaMin_C: -55°C; TaMax_C: 150°C; SizeArea_mm2: 0.5; SizeAreaWB_mm2: 3; SizeX_mm: 1; SizeZ_mm: 0.6; AEC Category: Q200
D1 D6 = CMP-0002934-2: LED, Rg, SMD; Manufacturer: Avago; Vf_V: 2.2V; Io_A: 20mA; Vr_V: 5V; Ir_A: 100µA; Tjmax_C: 85°C; Value1: W; LuminousIntensity_IV: 20; Angle: 120; U/M: EA
J1 = CMP-0054706-1: Header, 1x1, Tin, TH; Manufacturer: Sullins Connector Solutions; PartNumber: PEC01SAAN; CNHeader: FALSE; Current_A: 3A; Green_Lifecycle: Not Set; Shrouded: N; Gender: Male; Green_REACh: Incomplete; Voltage_V: 1.8kV; Row_Count: 1; Pitch_mm: 2.54; Cert_UL: Y
J2 = CMP-0054706-1: Header, 1x1, Tin, TH; Manufacturer: Sullins Connector Solutions; CNHeader: FALSE; Current_A: 3A; Green_Lifecycle: Not Set; Shrouded: N; Gender: Male; Green_REACh: Incomplete; Voltage_V: 1.8kV; Row_Count: 1; Pitch_mm: 2.54; Cert_UL: Y
J3 = CMP-0075404-1: Header, 100mil, 2x2, Gold, TH; Manufacturer: Samtec; Pitch_mm: 2.54; Gender: Male; Shrouded: N; Row_Count: 2; Current_A: 6.3A; Voltage_V: 550V; Cert_CSA: Y; CNHeader: True; CT: False; Green_Lifecycle: Active; Green_REACh: Passed
R1 R2 = CMP-0025750-4: RES, 200 k, 5%, 0.1 W, AEC-Q200 Grade 0, 0603; Manufacturer: Vishay-Dale; Power_W: 100mW; TempCo: 200 ppm/C; Value: 200k; EIA_Code: E24; SizeX_mm: 1.6; SizeY_mm: 0.8; SizeZ_mm: 1; Value2: 0.1W; SizeArea_mm2: 1.28; AEC Qualified: Y; VDC_V: 75V; AEC Category: Q200; AEC Grade: 0
R3 R4 = CMP-0025879-3: RES, 2.2 k, 5%, 0.1 W, AEC-Q200 Grade 0, 0603; Manufacturer: Panasonic; Power_W: 100mW; TempCo: 200 ppm/C; Value_Code: 2k20; U/M: EA; Value: 2.2k; EIA_Code: E24; SizeX_mm: 1.6; SizeY_mm: 0.8; SizeZ_mm: 1; Value2: 0.1W; SizeArea_mm2: 1.28; CompType: Resistor; AEC Qualified: Y; VDC_V: 75V; AEC Grade: 0; AEC Category: Q200
R5 = CMP-0021993-5: RES, 102, 1%, 0.1 W, AEC-Q200 Grade 0, 0603; Manufacturer: Vishay-Dale; Power_W: 100mW; TempCo: 100 ppm/C; Value_Code: 102R; Value: 102; SizeX_mm: 1.6; SizeY_mm: 0.8; SizeZ_mm: 1; Value2: 0.1W; SizeArea_mm2: 1.28; CompType: Resistor; AEC Qualified: Y; VDC_V: 75V; AEC Grade: 0; AEC Category: Q200; EIA_Code: E96
R6 = CMP-0025874-4: RES, 0, 5%, 0.1 W, AEC-Q200 Grade 0, 0603; Manufacturer: Panasonic; Power_W: 100mW; TempCo: 600 ppm/C; Value_Code: 0000; Value: 0; EIA_Code: E24; SizeX_mm: 1.6; SizeY_mm: 0.8; SizeZ_mm: 1; Value2: 0.1W; SizeArea_mm2: 1.28; AEC Qualified: Y; VDC_V: 50V; AEC Category: Q200; SizeAreaWB_mm2: 4.68
R7 = CMP-0025785-4: RES, 330, 5%, 0.1 W, AEC-Q200 Grade 0, 0603; Manufacturer: Vishay-Dale; Power_W: 100mW; TempCo: 200 ppm/C; Value_Code: 330R; Value: 330; EIA_Code: E24; SizeX_mm: 1.6; SizeY_mm: 0.8; SizeZ_mm: 1; Value2: 0.1W; SizeArea_mm2: 1.28; AEC Qualified: Y; VDC_V: 75V; AEC Category: Q200; AEC Grade: 0
R8-R11 R109 R110 = CMP-0026992-3: RES, 0, 5%, 0.1 W, AEC-Q200 Grade 0, 0402; Manufacturer: Panasonic; Power_W: 100mW; TempCo: 600 ppm/C; Value_Code: 0000; Value: 0; EIA_Code: E24; SizeX_mm: 1; SizeY_mm: 0.5; SizeZ_mm: 0.6; Value2: 0.1W; AEC Qualified: Y; VDC_V: 50V; AEC Category: Q200; SizeAreaWB_mm2: 3
R12 = CMP-0022237-4: RES, 24.9 k, 1%, 0.1 W, AEC-Q200 Grade 0, 0603; Manufacturer: Vishay-Dale; Power_W: 100mW; TempCo: 100 ppm/C; Value_Code: 24k9; Value: 24.9k; EIA_Code: E96; SizeX_mm: 1.6; SizeY_mm: 0.8; SizeZ_mm: 1; Value2: 0.1W; SizeArea_mm2: 1.28; AEC Qualified: Y; VDC_V: 75V; AEC Category: Q200; AEC Grade: 0
R13 R23 = CMP-0026822-3: RES, 0, 5%, 0.063 W, AEC-Q200 Grade 0, 0402; Manufacturer: Vishay-Dale; Value: 0; Value_Code: 0000; Power_W: 63mW; Value2: 0.063W; VDC_V: 50V; TempCo: 200 ppm/C; EIA_Code: E24; AEC Category: Q200; AEC Qualified: Y; SizeArea_mm2: 0.5; SizeX_mm: 1; SizeZ_mm: 0.6
R14-R17 = CMP-0027127-1: RES, 470, 5%, 0.05 W, 0201; Manufacturer: Yageo America; Power_W: 50mW; TempCo: 200 ppm/C; Value_Code: 470R; U/M: EA; Value: 470; EIA_Code: E24; SizeX_mm: 0.6; SizeY_mm: 0.3; SizeZ_mm: 0.26; Value2: 0.05W; SizeArea_mm2: 0.18; AEC Qualified: N; VDC_V: 25V; AEC Category: Q200
R20 = CMP-0026085-3: RES, 1.40 k, 1%, 0.063 W, AEC-Q200 Grade 0, 0402; Manufacturer: Vishay-Dale; Value: 1.40k; Res_ohm: 1.4k; Value_Code: 1k40; Power_W: 63mW; Value2: 0.063W; VDC_V: 50V; TempCo: 100 ppm/C; EIA_Code: E96; AEC Category: Q200; AEC Qualified: Y; AEC Grade: 0; SizeArea_mm2: 0.5; SizeX_mm: 1; SizeZ_mm: 0.6
R21 = CMP-0026100-2: RES, 1.00 M, 1%, 0.063 W, AEC-Q200 Grade 0, 0402; Manufacturer: Vishay-Dale; Value: 1.00Meg; Res_ohm: 1M; Value_Code: 1M00; Power_W: 63mW; Value2: 0.063W; VDC_V: 50V; TempCo: 100 ppm/C; EIA_Code: E96; AEC Category: Q200; AEC Qualified: Y; AEC Grade: 0; SizeArea_mm2: 0.5; SizeX_mm: 1; SizeZ_mm: 0.6
R22 = CMP-0026935-3: RES, 47 k, 5%, 0.063 W, AEC-Q200 Grade 0, 0402; Manufacturer: Vishay-Dale; Value: 47k; Value_Code: 47k0; Power_W: 63mW; Value2: 0.063W; VDC_V: 50V; TempCo: 200 ppm/C; EIA_Code: E24; AEC Category: Q200; AEC Qualified: Y; AEC Grade: 0; SizeArea_mm2: 0.5; SizeX_mm: 1; SizeZ_mm: 0.6
S1 = CMP-0002128-2: Switch, Slide, SPST 4 poles, SMT; Manufacturer: CTS Electrocomponents; CurrentRating_mA: 25A; PositionCount: 4; VDC_V: 24V; SwitchFunction: Off-On
S2 = CMP-0002170-2: Switch, Normally open, 2.3N force, 200k operations, SMD; Manufacturer: C&K Components; Circuit: SPST Switch; VDC_V: 32V; SwitchFunction: Off-Mom; PositionCount: 1; CurrentRating_mA: 1.001kA
U1 = CMP-0051649-3: Automotive Catalog Single Inverter, DBV0005A, LARGE T&R; Manufacturer: Texas Instruments; Generic Part Number: SN74LVC1G04-Q1; F @ Nom Voltage(Max)(Mhz): 150; tpd @ Nom Voltage(Max)(ns): 7.5,5.2,4.2,3.7; VCC(Max)(V): 5.5; Technology Family: LVC; Bits(#): 1; Output Drive (IOL/IOH)(Max)(mA): 32/-32; Output Type: CMOS; Logic: Inverting; Input Type: CMOS/TTL; Voltage(Nom)(V): 1.8,2.5,3.3,5; 3-State Output: No; VCC(Min)(V): 1.65; ICC @ Nom Voltage(Max)(mA): 0.01; AEC Category: Q200; AEC Qualified: Y; CompType: IC; SizeAreaWB_mm2: 14.82; SizeArea_mm2: 8.12; SizeX_mm: 2.8; SizeY_mm: 2.9; SizeZ_mm: 1.45; Green_Lifecycle: Active; Green_REACh: Passed
U2 U3 = CMP-0066434-1: Dual Bidirectional Multi-Voltage Level Translator, DQE0008A (X2SON-8); Alternate Manufacturer: Texas Instruments; SizeAreaWB_mm2: 4.8; U/M: EA; SizeZ_mm: 0.4; SizeX_mm: 1.0; SizeY_mm: 1.4; CompType: IC
U4 U5 = CMP-0079203-2: Fiber Optic Receiver 5MBd, TH; Manufacturer: Broadcom Limited; SizeAreaWB_mm2: 429.24; SizeArea_mm2: 345.44; SizeZ_mm: 10.2; SizeY_mm: 12.7; SizeX_mm: 27.2
U6 = CMP-0079202-2: Fiber Optic Transmitter 820nm, TH; Manufacturer: Broadcom Limited; SizeArea_mm2: 345.44; SizeAreaWB_mm2: 429.24; SizeY_mm: 12.7; SizeZ_mm: 10.2; SizeX_mm: 27.2
U7 U9 = CMP-0860319-1: 1-ch, 2:1 general-purpose analog multiplexer with 1.8-V logic control, DCK0006A (SOT-SC70-6); Alternate Manufacturer: Texas Instruments; SizeY_mm: 2; SizeArea_mm2: 4.2; SizeX_mm: 2.1; AEC Category: Q200; Rating: Catalog; CompType: IC; SizeZ_mm: 1.1; SizeAreaWB_mm2: 9.3; AEC Qualified: N
U8 = CMP-0038965-1: 25 MHz Mixed Signal Microcontroller with 128 KB Flash, 8192 B SRAM and 63 GPIOs, -40 to 85 degC, 80-pin QFP (PN), Green (RoHS & no Sb/Br); Manufacturer: Texas Instruments; ADC: 12-bit SAR; ADC Channels: 16; Brown Out Reset: Yes; DMA: 3; Flash(KB): 128; Frequency(MHz): 25; GPIO: 63; Multiplier: 32x32; SRAM(B): 8192; SubFamily: 5 Series; Timers - 16-bit: 4; USB: 1; USCI_A (UART/LIN/IrDA/SPI): 2
Y1 = CMP-0004637-3: as Y3 on sheet HSDC203A_Hub_EZFET

## Sheet HSDC203A_Breakout.SchDoc: Breakout Board
size B; Date: Not shown in title block; ApprovedBy: Not shown in title block; CheckedBy: Not shown in title block; Author: Not shown in title block; CompanyName: Not shown in title block; Engineer: Not shown in title block; Organization: Not shown in title block; Address1: Not shown in title block; Address2: Not shown in title block; Address3: Not shown in title block; Address4: Not shown in title block; DocumentNumber: 2; Revision: Use project parameter SCH_Rev; SheetNumber: 6; SheetTotal: 7; PageSetup: Record=PageOptions¦CenterHorizontal=True¦CenterVertical=True¦PrintScale=1.00¦XCorrection=1.00¦YCorrection=1.00¦PrintKind=0¦BorderSize=5000000¦LeftOffset=0¦BottomOffset=0¦Orientation=2¦PaperLength=1000¦PaperWidth=1000¦Scale=100¦PaperSource=15¦PrintQuality=600¦MediaType=1¦DitherType=10¦PaperKind=Letter¦PrintScaleMode=1
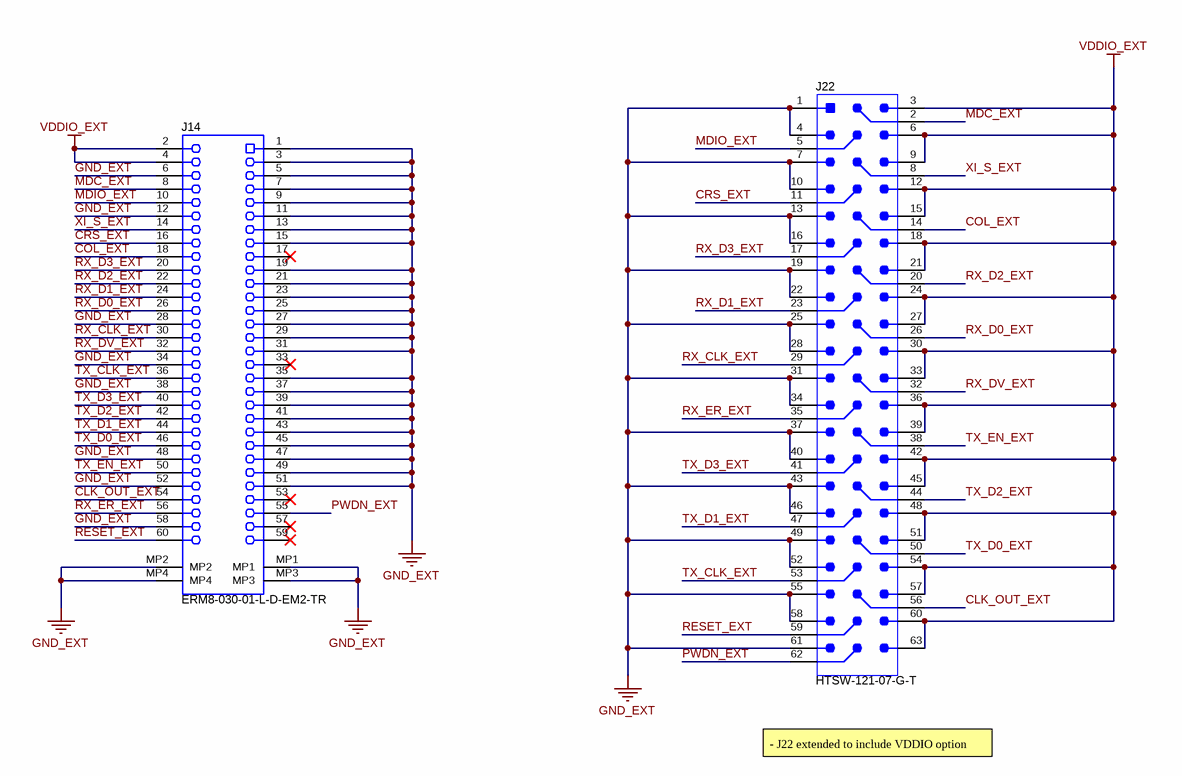
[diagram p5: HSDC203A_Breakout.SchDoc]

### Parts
J14  ERM8-030-01-L-D-EM2-TR  [Samtec_ERM8-030-01-L-D-EM2]
J22  HTSW-121-07-G-T  [Samtec_HTSW-121-07-x-T]

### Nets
GND_EXT: J14.1 J14.3 J14.5 J14.6 J14.7 J14.9 J14.11 J14.12 J14.13 J14.15 J14.19 J14.21 J14.23 J14.25 J14.27 J14.28 J14.29 J14.31 J14.34 J14.35 J14.37 J14.38 J14.39 J14.41 J14.43 J14.45 J14.47 J14.48 J14.49 J14.51 J14.52 J14.58 J14.MP1 J14.MP2 J14.MP3 J14.MP4 J22.1 J22.4 J22.7 J22.10 J22.13 J22.16 J22.19 J22.22 J22.25 J22.28 J22.31 J22.34 J22.37 J22.40 J22.43 J22.46 J22.49 J22.52 J22.55 J22.58 J22.61
VDDIO_EXT: J14.2 J14.4 J22.3 J22.6 J22.9 J22.12 J22.15 J22.18 J22.21 J22.24 J22.27 J22.30 J22.33 J22.36 J22.39 J22.42 J22.45 J22.48 J22.51 J22.54 J22.57 J22.60 J22.63
CLK_OUT_EXT: J14.54 J22.56
COL_EXT: J14.18 J22.14
CRS_EXT: J14.16 J22.11
MDC_EXT: J14.8 J22.2
MDIO_EXT: J14.10 J22.5
PWDN_EXT: J14.55 J22.62
RESET_EXT: J14.60 J22.59
RX_CLK_EXT: J14.30 J22.29
RX_D0_EXT: J14.26 J22.26
RX_D1_EXT: J14.24 J22.23
RX_D2_EXT: J14.22 J22.20
RX_D3_EXT: J14.20 J22.17
RX_DV_EXT: J14.32 J22.32
RX_ER_EXT: J14.56 J22.35
TX_CLK_EXT: J14.36 J22.53
TX_D0_EXT: J14.46 J22.50
TX_D1_EXT: J14.44 J22.47
TX_D2_EXT: J14.42 J22.44
TX_D3_EXT: J14.40 J22.41
TX_EN_EXT: J14.50 J22.38
XI_S_EXT: J14.14 J22.8

Not connected (* = marked no-connect by the designer): J14 17* 33* 53* 57* 59*

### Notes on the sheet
- - J22 extended to include VDDIO option

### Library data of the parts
J14 = CMP-0055619-1: Receptacle, 0.8mm, 30x2, Tin, Edge mount; Manufacturer: Samtec; CNHeader: FALSE; Current_A: 2.2A; Gender: Female; Voltage_V: 200V; Row_Count: 2; Pitch_mm: 0.8; Cert_UL: Y
J22 = CMP-0084401-1: Header, 2.54mm, 21x3, Gold, TH; Manufacturer: Samtec; RowSpacing_mm: 2.54; Cert_UL: Y; Gender: Male; Shrouded: N; Row_Count: 3

## Sheet HSDC203A_Hardware.SchDoc: Hardware Page
size 431 x 279 mm; Date: Not shown in title block; ApprovedBy: Not shown in title block; CheckedBy: Not shown in title block; Author: Not shown in title block; CompanyName: Not shown in title block; Engineer: Not shown in title block; Organization: Not shown in title block; Address1: Not shown in title block; Address2: Not shown in title block; Address3: Not shown in title block; Address4: Not shown in title block; Revision: Use project parameter SCH_Rev; SheetNumber: 7; SheetTotal: 7; PageSetup: Record=PageOptions¦CenterHorizontal=True¦CenterVertical=True¦PrintScale=1.00¦XCorrection=1.00¦YCorrection=1.00¦PrintKind=0¦BorderSize=5000000¦LeftOffset=0¦BottomOffset=0¦Orientation=2¦PaperLength=1000¦PaperWidth=1000¦Scale=100¦PaperSource=15¦PrintQuality=600¦MediaType=1¦DitherType=10¦PaperKind=Letter¦PrintScaleMode=1
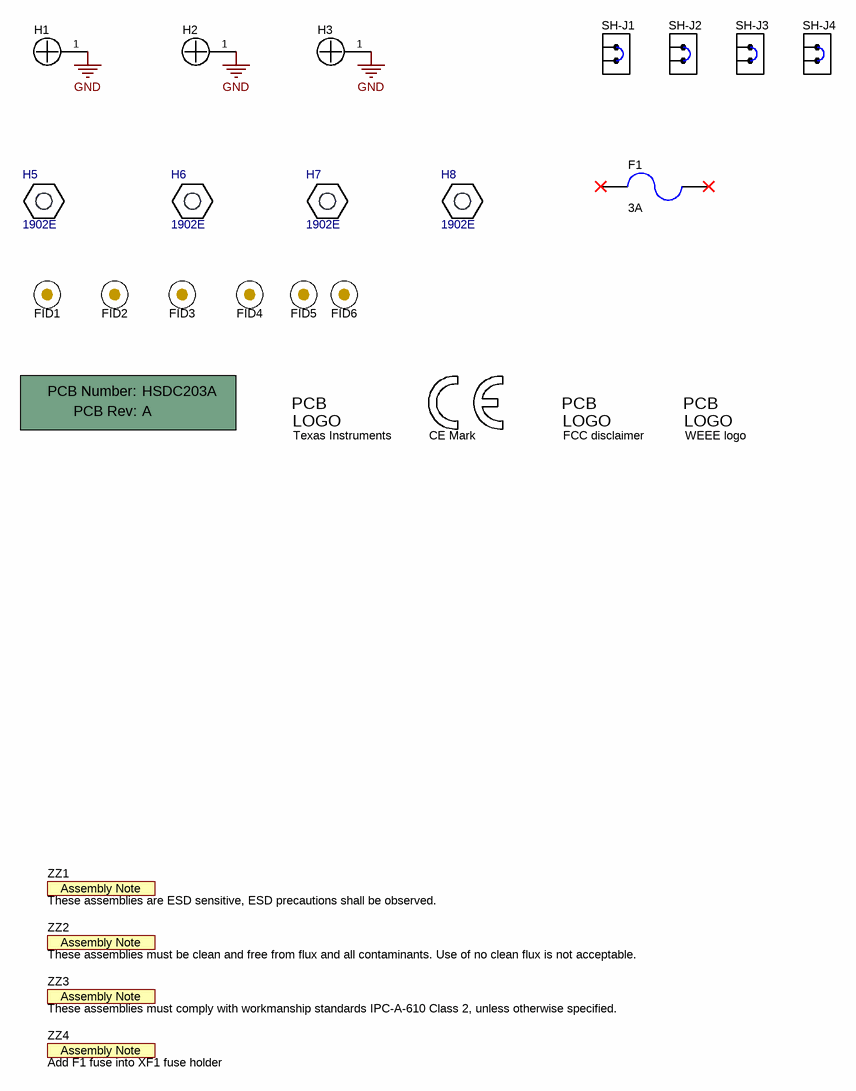
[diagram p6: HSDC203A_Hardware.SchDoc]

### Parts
!PCB1  Printed Circuit Board  (value not drawn)  (mechanical)
F1  3402.0014.11  [Fuse_3402]  (value not drawn)  (mechanical)
FID1  Fiducial  [Fiducial10-20]  (value not drawn)
FID2  Fiducial  [Fiducial10-20]  (value not drawn)
FID3  Fiducial  [Fiducial10-20]  (value not drawn)
FID4  Fiducial  [Fiducial10-20]  (value not drawn)
FID5  Fiducial  [Fiducial10-20]  (value not drawn)
FID6  Fiducial  [Fiducial10-20]  (value not drawn)
H1  NY PMS 440 0025 PH  [NY PMS 440 0025 PH]  (value not drawn)
H2  NY PMS 440 0025 PH  [NY PMS 440 0025 PH]  (value not drawn)
H3  NY PMS 440 0025 PH  [NY PMS 440 0025 PH]  (value not drawn)
H5  1902E  [Keystone_1902E]
H6  1902E  [Keystone_1902E]
H7  1902E  [Keystone_1902E]
H8  1902E  [Keystone_1902E]
Logo1  CE Mark  [CE_Mark_5mm]  (no BOM)
Logo2  Texas Instruments  [TI_Stacked_Overlay_Small]  (no BOM)
Logo3  FCC disclaimer  [FCC_disclaimer]  (no BOM)
Logo4  WEEE logo  [WEEE_Minimum]  (no BOM)
SH-J1  M7582-05  [Harwin_M7582-05]  (value not drawn)
SH-J2  M7582-05  [Harwin_M7582-05]  (value not drawn)
SH-J3  M7582-05  [Harwin_M7582-05]  (value not drawn)
SH-J4  M7582-05  [Harwin_M7582-05]  (value not drawn)
ZZ1  These assemblies are ESD sensitive, ESD precautions shall be observed.  [AssemblyNote]  (no BOM)
ZZ2  These assemblies must be clean and free from flux and all contaminants. Use of no clean flux is not acceptable.  [AssemblyNote]  (no BOM)
ZZ3  These assemblies must comply with workmanship standards IPC-A-610 Class 2, unless otherwise specified.  [AssemblyNote]  (no BOM)
ZZ4  Add F1 fuse into XF1 fuse holder  [AssemblyNote]  (no BOM)

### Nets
GND: H1.1 H2.1 H3.1

Not connected (* = marked no-connect by the designer): F1 1* 2*

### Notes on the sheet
- (near F1) 3A

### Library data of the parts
!PCB1 = CMP-0003618-2: Manufacturer: Any; PartNumber: HSDC203A; CompType: PCB
F1 = CMP-0077257-2: Fuse, 3 A, 63VAC/VDC, SMD; Manufacturer: Schurter; VAC_V: 63V; SizeAreaWB_mm2: 47.94; SizeArea_mm2: 22.94; MeltingTyp: 1.3; Irating_A: 3A; SizeZ_mm: 2.6; SizeY_mm: 3.1; SizeX_mm: 7.4
FID1-FID6 = CMP-0077181-1: Fiducial mark.  There is nothing to buy or mount.
H1-H3 = CMP-0003617-1: Machine Screw, Round, #4-40 x 1/4, Nylon, Philips panhead; Manufacturer: B&F Fastener Supply; CompType: Hardware
H5-H8 = CMP-0003611-1: Standoff, Hex, 1"L #4-40 Nylon; Manufacturer: Keystone; CompType: Hardware
Logo1 = CMP-0074844-1: SymbolCreator: a0412235
Logo2 = CMP-0074838-1: Texas Instrument Corporate Signature; SymbolCreator: a0412235; Lib Reference: TI_Logo; Library Reference: Logo
Logo3 = CMP-0074847-1: FCC_disclaimer; Library Reference: Logo
Logo4 = CMP-0074769-1
SH-J1-SH-J4 = CMP-0078738-1: Single Operation 2.54mm Pitch Open Top Jumper Socket; Manufacturer: Harwin
ZZ1 = CMP-0077236-1
ZZ2 = CMP-0077237-1
ZZ3 = CMP-0077238-1
ZZ4 = CMP-0077238-1: These assemblies must comply with workmanship standards IPC-A-610 Class 2, unless otherwise specified.

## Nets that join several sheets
3V3_OPT: HSDC203A_Power (J9.2), HSDC203A_Coms (R2.2 R3.2 R4.2 U1.5)
5V: HSDC203A_Power (7 pins), HSDC203A_Coms (6 pins)
GND: HSDC203A_Power (48 pins), HSDC203A_Main (85 pins), HSDC203A_Hub_EZFET (57 pins), HSDC203A_Coms (47 pins), HSDC203A_Hardware (H1.1 H2.1 H3.1)
MCU_VCC: HSDC203A_Power (6 pins), HSDC203A_Hub_EZFET (17 pins), HSDC203A_Coms (8 pins)
USB_VBUS: HSDC203A_Power (5 pins), HSDC203A_Hub_EZFET (D7.1 R89.2 U16.53), HSDC203A_Coms (5 pins)
VDDA3P3: HSDC203A_Power (J7.2), HSDC203A_Main (R41.2)
VDDIO: HSDC203A_Power (J8.2), HSDC203A_Main (7 pins), HSDC203A_Coms (U2.2 U3.2)
MDC: HSDC203A_Main (R18.1 U14.12), HSDC203A_Coms (J1.1 R109.1 U3.3)
MDIO: HSDC203A_Main (R19.1 R47.1 U14.11), HSDC203A_Coms (J2.1 R110.1 U3.4)
PWDN: HSDC203A_Main (J18.55 U14.21), HSDC203A_Coms (U2.3)
RESET: HSDC203A_Main (5 pins), HSDC203A_Coms (U2.4)
RST/SBWTDIO: HSDC203A_Hub_EZFET (R95.2), HSDC203A_Coms (5 pins)
TARGET_D_N: HSDC203A_Hub_EZFET (C71.2 R63.1), HSDC203A_Coms (U8.64)
TARGET_D_P: HSDC203A_Hub_EZFET (C70.2 R66.1), HSDC203A_Coms (R20.2 U8.62)
TEST/SBWTCK: HSDC203A_Hub_EZFET (R94.2), HSDC203A_Coms (J3.1 U8.71)

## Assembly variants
001: not fitted C1 C2 C3 C4 C5 C6 C45 C55 C60 C89 C92 C93 C94 C95 C96 C97 C98 C? FID1 FID2 FID3 FID4 FID5 FID6 J1 J2 J16 R1 R2 R3 R4 R5 R6 R7 R8 R9 R10 R11 R30 R35 R39 R42 R50 R105 R107 R114 U1 U2 U3 U4 U5 U6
